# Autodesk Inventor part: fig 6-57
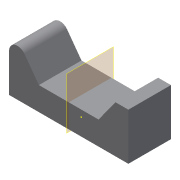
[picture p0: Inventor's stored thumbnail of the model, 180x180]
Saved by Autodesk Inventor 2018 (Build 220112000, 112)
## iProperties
Created: 2011-07
Part Number: fig 6-57
Material: Generic
Document SubType Name: Modeling
Designer: CadCim
Density: 1 g/cm^3
Appearance: Default
Author: CadCim
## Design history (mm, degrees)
sketch "Sketch1"
  geometry: 1 further point
sketch "Sketch2"
  geometry: L1 (3, -4)-(17, -4); L2 (17, -4)-(17, 7); L3 (17, 7)-(14, 7); L4 (14, 7)-(10, 1.5); L5 (10, 1.5)-(3, 1.5); L6 (3, -4)-(-11, -4); L7 (-11, -4)-(-11, 7); L8 (-11, 7)-(-8, 7); L9 (-8, 7)-(-4, 1.5); L10 (-4, 1.5)-(3, 1.5); 1 further point
  constraints: 20 end point, 2 parallel, 1 perpendicular
extrude "Extrusion1" new body sketch "Sketch2" distance "d0" = 10; taper "d1" = 0 deg
fillet "Fillet1" dims "d2" = 2
workplane "Work Plane1"
body "Solid1"
